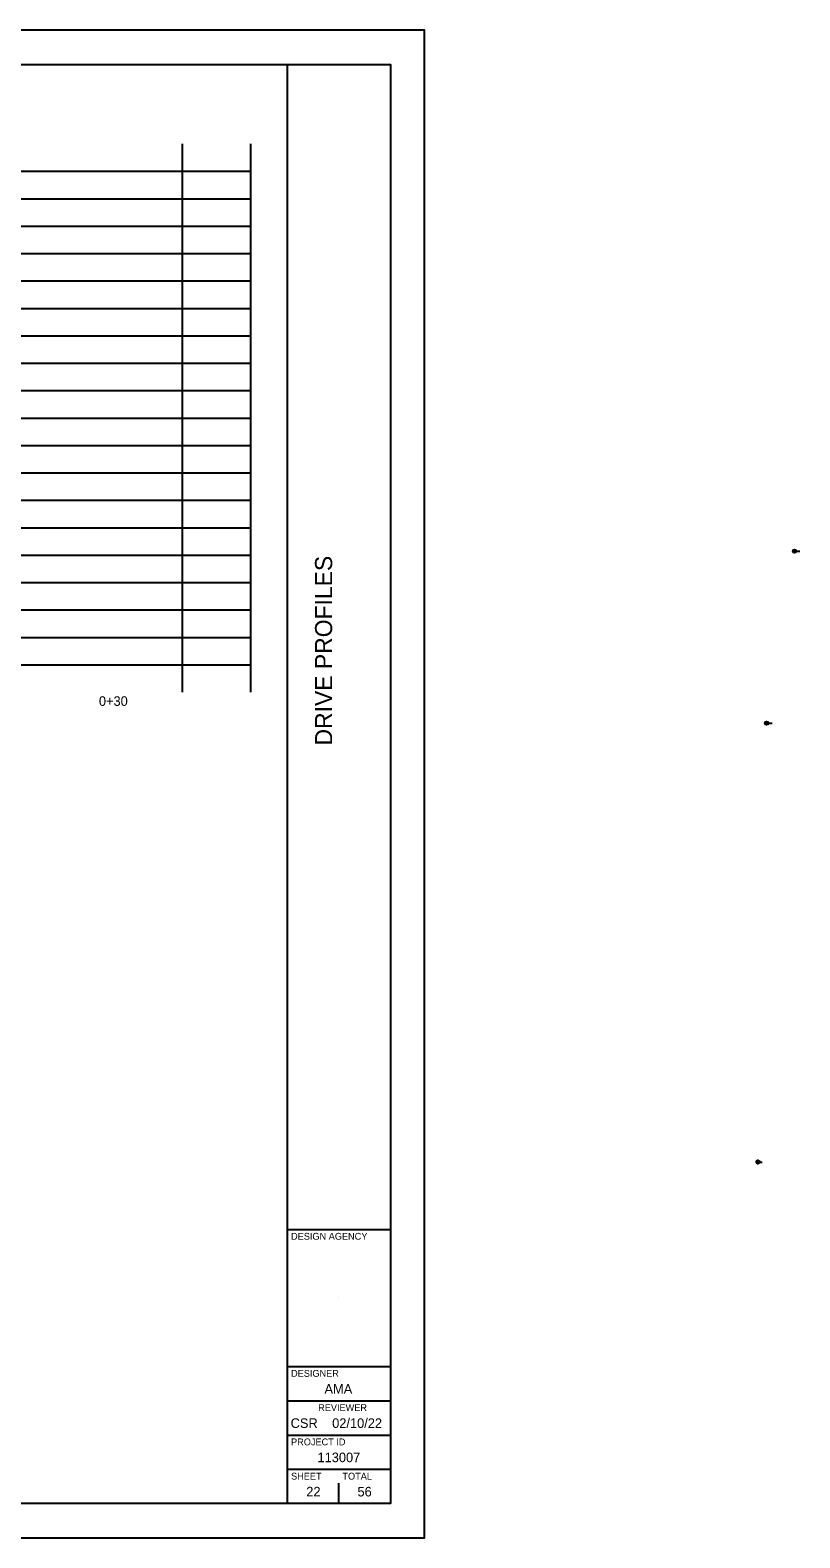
# Model space of a CAD drawing. Extents: x 0 to 461, y 0 to 110.
# Drawn here: x 141.2 to 197.4, y 0 to 110 of the extents above; entities that cross this region are included whole.
import ezdxf

# ---------------------------------------------------------------- set-up
doc = ezdxf.new("R2010")
doc.units = 0
for name, color, linetype in [('Default', 7, 'Continuous'), ('PF_P_Sta_Elev_Text', 7, 'Continuous'), ('PV_P_Drive', 7, 'Continuous'), ('SH_Border', 7, 'Continuous'), ('SH_Cut_Line', 7, 'Continuous'), ('SH_Data', 7, 'Continuous'), ('SH_Major_Grid_Line', 7, 'Continuous')]:
    doc.layers.add(name, color=color, linetype=linetype)

msp = doc.modelspace()

# ---------------------------------------------------------------- linework, layer by layer
at = {"layer": 'Default'}
for p, q in [((194.21, 27.42), (194.47, 27.42)), ((194.34, 27.42), (194.65, 27.42))]:
    msp.add_line(p, q, dxfattribs=at)
msp.add_circle((194.34, 27.42), 0.13, dxfattribs=at)
at = {"layer": 'PV_P_Drive'}
for p, q in [((196.88, 71.99), (197.14, 71.99)), ((197.01, 71.99), (197.4, 71.99)), ((194.84, 59.44), (195.1, 59.44)), ((194.97, 59.44), (195.37, 59.44))]:
    msp.add_line(p, q, dxfattribs=at)
for centre in [(197.01, 71.99), (194.97, 59.44)]:
    msp.add_circle(centre, 0.13, dxfattribs=at)
at = {"layer": 'SH_Border'}
for p, q in [((160, 2.5), (160, 107.5)), ((160, 22.5), (167.5, 22.5)), ((160, 12.5), (167.5, 12.5)), ((160, 10), (167.5, 10)), ((160, 7.5), (167.5, 7.5)), ((160, 5), (167.5, 5))]:
    msp.add_line(p, q, dxfattribs=at)
msp.add_lwpolyline([(7.5, 107.5), (167.5, 107.5), (167.5, 2.5), (7.5, 2.5)], close=True, dxfattribs=at)
at = {"layer": 'SH_Cut_Line'}
msp.add_lwpolyline([(0, 0), (170, 0), (170, 110), (0, 110)], close=True, dxfattribs=at)
at = {"layer": 'SH_Data'}
for p, q in [((163.75, 17.5), (163.75, 17.5)), ((161.87, 3.38), (161.87, 3.38)), ((163.75, 2.5), (163.75, 4))]:
    msp.add_line(p, q, dxfattribs=at)
at = {"layer": 'SH_Major_Grid_Line'}
for p, q in [((152.32, 61.7), (152.32, 101.7)), ((157.32, 61.7), (157.32, 101.7)), ((117.32, 99.7), (157.32, 99.7)), ((117.32, 97.7), (157.32, 97.7)), ((117.32, 95.7), (157.32, 95.7)), ((117.32, 93.7), (157.32, 93.7)), ((117.32, 91.7), (157.32, 91.7)), ((117.32, 89.7), (157.32, 89.7)), ((117.32, 87.7), (157.32, 87.7)), ((117.32, 85.7), (157.32, 85.7)), ((117.32, 83.7), (157.32, 83.7)), ((117.32, 81.7), (157.32, 81.7)), ((117.32, 79.7), (157.32, 79.7)), ((117.32, 77.7), (157.32, 77.7)), ((117.32, 75.7), (157.32, 75.7)), ((117.32, 73.7), (157.32, 73.7)), ((117.32, 71.7), (157.32, 71.7)), ((117.32, 69.7), (157.32, 69.7)), ((117.32, 67.7), (157.32, 67.7)), ((117.32, 65.7), (157.32, 65.7)), ((117.32, 63.7), (157.32, 63.7))]:
    msp.add_line(p, q, dxfattribs=at)

# ---------------------------------------------------------------- texts
at = {"layer": 'Default'}
for s, p in [('10', (194.32, 27.45)), ('21', (194.33, 27.37)), ('Drawing', (194.5, 27.45)), ('CUSTOM 1.8:1', (194.5, 27.37))]:
    msp.add_text(s, height=0.0164, dxfattribs=at).set_placement(p)
at = {"layer": 'PF_P_Sta_Elev_Text'}
msp.add_text('0+30', height=0.7, dxfattribs=at).set_placement((146.22, 60.7))
at = {"layer": 'PV_P_Drive'}
for s, p in [('21', (197, 71.94)), ('1', (197, 72.02)), ('CLP_Drive4 - Profile 2', (197.17, 72.02)), ('1:5', (197.17, 71.94)), ('11', (194.96, 59.47)), ('21', (194.96, 59.39)), ('CLP_Drive6 - Profile 1-1', (195.13, 59.47)), ('1:5', (195.13, 59.39))]:
    msp.add_text(s, height=0.0164, dxfattribs=at).set_placement(p)
at = {"layer": 'SH_Data'}
msp.add_text('DRIVE PROFILES', height=1.25, rotation=90, dxfattribs=at).set_placement((163.25, 57.81))
for s, height, p in [('DESIGN AGENCY', 0.5, (160.25, 21.75)), ('DESIGNER', 0.5, (160.25, 11.75)), ('AMA', 0.7, (162.69, 10.52)), ('REVIEWER', 0.5, (162.23, 9.25)), ('CSR', 0.7, (160.22, 8.02)), ('02/10/22', 0.7, (163.25, 8.02)), ('PROJECT ID', 0.5, (160.25, 6.75)), ('113007', 0.7, (162.18, 5.52)), ('SHEET', 0.5, (160.25, 4.25)), ('TOTAL', 0.5, (164, 4.25)), ('22', 0.7, (161.36, 3.02)), ('56', 0.7, (165.1, 3.02))]:
    msp.add_text(s, height=height, dxfattribs=at).set_placement(p)

doc.saveas('drawing.dxf')
